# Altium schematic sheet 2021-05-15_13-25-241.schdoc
size 217 x 116 mm; SheetNumber: 1; SheetTotal: 1
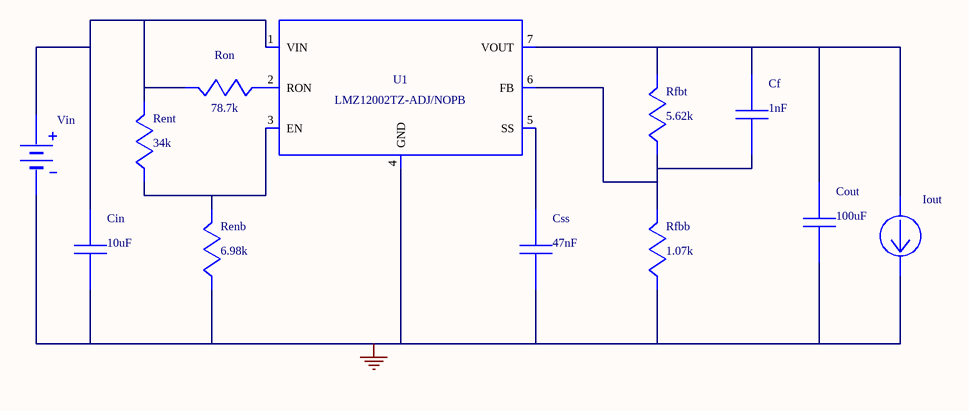
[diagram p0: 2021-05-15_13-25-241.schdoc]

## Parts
Cf  value 1nF  (hidden comment: GRM1555C1H102JA01J)
Cin  value 10uF  (hidden comment: GRM21BR61E106MA73L)
Cout  value 100uF  (hidden comment: C3216X5R1A107M160AC)
Css  value 47nF  (hidden comment: GRM21BR71H473KA01L)
Iout  WB_CURRENT_LOAD  (value not drawn)
Renb  value 6.98k  (hidden comment: ERJ-6ENF6981V)
Rent  value 34k  (hidden comment: CRCW080534K0FKEA)
Rfbb  value 1.07k  (hidden comment: ERJ-6ENF1071V)
Rfbt  value 5.62k  (hidden comment: ERJ-6ENF5621V)
Ron  value 78.7k  (hidden comment: CRCW080578K7FKEA)
U1  LMZ12002TZ-ADJ/NOPB
Vin  WB_BATTERY  (value not drawn)

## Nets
0: Cin.2 Cout.2 Css.2 Iout.2(-) Renb.2 Rfbb.2 U1.4(GND) U1.8(EP) Vin.2(-)
NetCf_1: Cf.1 Cout.1 Iout.1(+) Rfbt.1 U1.7(VOUT)
NetCf_2: Cf.2 Rfbb.1 Rfbt.2 U1.6(FB)
NetCin_1: Cin.1 Rent.1 Ron.1 U1.1(VIN) Vin.1(+)
NetCss_1: Css.1 U1.5(SS)
NetRenb_1: Renb.1 Rent.2 U1.3(EN)
NetRon_2: Ron.2 U1.2(RON)

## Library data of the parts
Cf = GRM1555C1H102JA01J: GRM1555C1H102JA0; Manufacturer Name: MuRata
Cin = GRM21BR61E106MA73L: GRM21BR61E106MA7; Manufacturer Name: MuRata
Cout = C3216X5R1A107M160AC: C3216X5R1A107M16; Manufacturer Name: TDK
Css = GRM21BR71H473KA01L: GRM21BR71H473KA0; Manufacturer Name: MuRata
Renb = ERJ-6ENF6981V: Manufacturer Name: Panasonic
Rent = CRCW080534K0FKEA: Manufacturer Name: Vishay-Dale
Rfbb = ERJ-6ENF1071V: Manufacturer Name: Panasonic
Rfbt = ERJ-6ENF5621V: Manufacturer Name: Panasonic
Ron = CRCW080578K7FKEA: Manufacturer Name: Vishay-Dale
U1 = LMZ12002TZ-ADJ/NOPB: LMZ12002TZ-ADJ/N; Manufacturer Name: Texas Instruments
